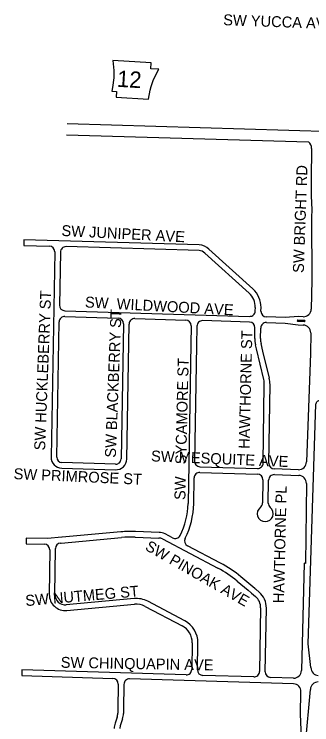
# Model space of a CAD drawing. Extents: x 0 to 712119, y 0 to 761125.
# Drawn here: x 652253 to 653613, y 733617 to 736871 of the extents above; entities that cross this region are included whole.
import ezdxf

# ---------------------------------------------------------------- set-up
doc = ezdxf.new("R2010")
doc.units = 0
for name, color, linetype in [('HWY signs', 7, 'Continuous'), ('PAVED ROADS', 7, 'Continuous'), ('street names', 7, 'Continuous')]:
    doc.layers.add(name, color=color, linetype=linetype)

msp = doc.modelspace()

# ---------------------------------------------------------------- linework, layer by layer
at = {"layer": 'HWY signs'}
msp.add_lwpolyline([(652867.2, 736482.6), (652873.6, 736523), (652878.3, 736540.7), (652888.6, 736567.4), (652899.3, 736589.8), (652914.1, 736618.9), (652877.1, 736621.1), (652878.8, 736648.5), (652703.3, 736659.1), (652708.8, 736613.5), (652708.2, 736580.4), (652702.7, 736536.1), (652699.7, 736518.6), (652719.9, 736517.4), (652718.4, 736491.6)], close=True, dxfattribs=at)
at = {"layer": 'PAVED ROADS'}
for points in [[(653710.8, 736333.1), (652495, 736368.5)], [(652492.3, 736318.6), (653597.7, 736286.4)], [(653612.4, 736256.3), (653610.7, 736117.7), (653610.7, 736039.1), (653612.6, 735974.7), (653612.1, 735941), (653612.1, 735941), (653612.8, 735653.9), (653610.4, 735520.7)], [(653098.6, 735814.5), (652296.6, 735838.5), (652296.2, 735812.5), (652412.9, 735809)], [(652437.7, 735783.1), (652421.2, 734842.8)], [(652463.6, 735781.6), (652459.4, 735539)], [(653097.8, 735788.5), (652489.9, 735806.7)], [(653343.7, 735613.3), (653142.3, 735794.9)], [(653326.3, 735594), (653123.4, 735777.1)], [(653354.8, 735512.4), (653355, 735527.9)], [(653380.7, 735510.9), (653381, 735527.4)], [(652484.1, 735513.1), (653328.5, 735487.3)], [(652484.3, 735487), (652727.2, 735479.6)], [(652447.2, 734842.3), (652458, 735462)], [(652804.2, 735477.3), (653037.1, 735470.2)], [(653328.7, 735461.3), (653114.1, 735467.9)], [(653573.8, 735485.9), (653551.6, 735486.6), (653491.5, 735482.4), (653405.5, 735485)], [(653405.7, 735459), (653490.7, 735456.4), (653550.5, 735448.6), (653550.5, 735448.6)], [(653579.3, 735463.7), (653549.3, 735464.6)], [(653549.5, 735470.6), (653579.5, 735469.7)], [(653579.3, 735463.7), (653579.3, 735463.7)], [(652751.9, 735453.7), (652741.1, 734834.3)], [(652767.1, 734833.9), (652777.9, 735452.3)], [(653061.8, 735444.3), (653060.3, 735360), (653047.3, 734630.1)], [(653087.8, 735442.8), (653086.2, 735353.9), (653076.7, 734824.9)], [(653352.5, 735386.1), (653353.4, 735435.4)], [(653378.5, 735385.7), (653379.4, 735433.9)], [(653550.5, 735448.6), (653573.9, 735447.9)], [(653608.4, 735411.7), (653606.6, 735317.9), (653588.9, 734821)], [(653360.1, 735339.3), (653355.7, 735357.8)], [(653419, 735203.9), (653389.4, 735328.5), (653380.9, 735363.8)], [(653393.7, 735197.8), (653360.1, 735339.3)], [(653390.7, 734816.1), (653396.1, 735176.2)], [(653416.7, 734814.5), (653422.1, 735175.8)], [(653609, 733878.9), (653596.4, 733988.2), (653632.3, 735085.4), (653633, 735089.1), (653634.3, 735092.6), (653636.3, 735095.8), (653638.8, 735098.7), (653641.8, 735101), (653645.2, 735102.7), (653648.8, 735103.8), (653652.5, 735104.2), (653669.6, 735105.8), (653705.1, 735106), (653712.9, 735106), (653721.7, 735105.8), (653769.3, 735104.4), (653783.5, 735104), (653814.4, 735103.1), (653842.7, 735102.3), (653872.2, 735101.1), (653896.8, 735100), (653930.7, 735098.6), (653954, 735097.9), (653976.4, 735097.2)], [(652716.4, 734810.8), (652470.5, 734817.9)], [(652469.7, 734791.9), (652715.6, 734784.8)], [(653101.4, 734799), (653364.5, 734791)], [(653101.6, 734772.9), (653364.9, 734765)], [(653551.8, 734785.3), (653441.5, 734788.6)], [(653073.3, 734629.6), (653075.3, 734747.9)], [(653389.6, 734739.1), (653388, 734632.8)], [(653441.9, 734762.6), (653553.3, 734759.2)], [(653414, 734632.4), (653415.6, 734737.5)], [(653588.2, 734722.4), (653584, 734355.3), (653578.2, 734356.9), (653565.8, 733865.3)], [(652740.3, 734500.6), (652472.3, 734476.1), (652470.6, 734476.1), (652405, 734470.1), (652308.1, 734471.5), (652307.2, 734445.5), (652389.8, 734444.3)], [(652915.1, 734498.3), (652806.5, 734502.4)], [(652976.5, 734473), (652942.1, 734491.1)], [(652464.2, 734449.4), (652467.3, 734449.5), (652742.7, 734474.7)], [(652805.5, 734476.4), (652914.1, 734472.3)], [(652930, 734468.1), (653184.1, 734334.2)], [(652414.9, 734418.5), (652413, 734214.1)], [(652439, 734213.8), (652441, 734424.6), (652441, 734424.6)], [(653196.2, 734357.2), (653044.6, 734437.1)], [(653372.4, 734224.4), (653356.6, 734237.8), (653356.3, 734238), (653352.1, 734241.6), (653288.6, 734294.9)], [(653271.8, 734275), (653322, 734233), (653336, 734221.1), (653337.3, 734220.1), (653355.6, 734204.5)], [(652800.4, 734195), (652490.3, 734166.6)], [(652492.7, 734140.7), (652802.8, 734169.1)], [(652851.3, 734159.5), (653020, 734070.6)], [(653032.1, 734093.6), (652863.4, 734182.5)], [(653379.3, 734152.2), (653374.3, 733861.3)], [(653400.2, 733859.8), (653405.3, 734151.8)], [(653066.5, 733992.1), (653064.4, 733870.7)], [(653090.4, 733869.2), (653092.5, 733991.7)], [(653038.1, 733845.6), (652288.2, 733868.4), (652287.4, 733842.3), (652703.4, 733829.8)], [(653529.9, 733804.7), (652780.4, 733827.4)], [(653348, 733836.2), (653115.1, 733843.3)], [(653530, 733830.7), (653425, 733833.9)], [(652728.2, 733803.8), (652726.2, 733688.7), (652726, 733669.9)], [(652754.1, 733802.4), (652752.3, 733688), (652752, 733669.5)], [(653623.9, 731094.8), (653552.8, 731124.8), (653532.2, 731177.3), (653583.8, 733527.6), (653606.8, 733778.9)], [(653565.2, 733547.2), (653565.3, 733557.3), (653560.8, 733665.2), (653563.4, 733768.4)], [(652722.9, 733651.8), (652714.2, 733625.2)], [(652747.6, 733643.7), (652739, 733617.1)]]:
    msp.add_lwpolyline(points, dxfattribs=at)
for centre, radius, start, end in [((653572.1, 736255.2), 40.3, 1.4945, 50.5503), ((653096.7, 735751.5), 63, 43.5707, 88.2844), ((652412.2, 735783.5), 25.5, 358.9967, 88.2861), ((652489.1, 735781.2), 25.5, 88.2861, 178.9967), ((653096.7, 735751.5), 37, 43.6506, 88.289), ((653268, 735529.4), 87, 358.9967, 47.947), ((653268, 735529.4), 113, 358.9967, 47.947), ((652484.9, 735538.5), 25.5, 178.9967, 268.256), ((653574.9, 735521.4), 35.5, 268.256, 358.9459), ((652483.5, 735461.5), 25.5, 88.256, 178.9967), ((653329.3, 735512.8), 25.5, 268.256, 358.9967), ((653406.2, 735510.5), 25.5, 178.9967, 268.247), ((652726.4, 735454.2), 25.5, 358.9967, 88.256), ((652803.4, 735451.8), 25.5, 88.256, 178.9967), ((653036.3, 735444.7), 25.5, 358.9967, 88.256), ((653113.3, 735442.4), 25.5, 88.256, 178.9984), ((653327.9, 735435.8), 25.5, 358.9967, 88.256), ((653404.9, 735433.5), 25.5, 88.256, 178.9967), ((653549.4, 735467.6), 3, 88.256, 268.256), ((653579.4, 735466.7), 3, 268.256, 88.256), ((653572.9, 735412.4), 35.5, 358.9459, 88.256), ((653465.5, 735384.1), 113, 178.9967, 193.5079), ((653465.5, 735384.1), 87, 178.9967, 193.5079), ((653309.1, 735177.5), 87, 359.1486, 13.5154), ((653309.1, 735177.5), 113, 359.1486, 13.5154), ((652471.2, 734841.9), 50, 178.9967, 268.3309), ((652471.2, 734841.9), 24, 178.9967, 268.3309), ((652717.1, 734834.8), 50, 268.3212, 358.9967), ((652717.1, 734834.8), 24, 268.3106, 358.9967), ((653102.2, 734824.4), 25.5, 179.0042, 268.2635), ((653365.2, 734816.5), 25.5, 268.2635, 359.1486), ((653442.2, 734814.1), 25.5, 179.1486, 268.2635), ((653552.9, 734821.3), 36, 268.2589, 359.5444), ((653100.8, 734747.4), 25.5, 88.2635, 179.0042), ((653364.1, 734739.5), 25.5, 359.1486, 88.2635), ((653441.1, 734737.1), 25.5, 88.2635, 179.1486), ((653552.2, 734723.3), 36, 358.5596, 88.2627), ((652710.3, 734636), 337, 333.2055, 359.0042), ((652710.3, 734636), 363, 333.0106, 359.0042), ((653400.3, 734584), 36.5, 127.5354, 50.7617), ((653362.5, 734633.2), 25.5, 307.5354, 359.1486), ((653439.5, 734632.1), 25.5, 179.1486, 230.7617), ((652787.1, 733989.8), 513, 87.8333, 95.2353), ((652912.7, 734435.3), 63, 62.222, 87.8333), ((652988.4, 734495.5), 25.5, 242.222, 333.2055), ((652465.8, 734424.6), 24.8, 93.6678, 180.0831), ((652787.1, 733989.8), 487, 87.8333, 95.2353), ((652912.7, 734435.3), 37, 62.222, 87.8333), ((653056.5, 734459.6), 25.5, 153.0106, 242.222), ((652389.4, 734418.8), 25.5, 359.4675, 89.1582), ((652957.2, 733903.3), 513, 49.7492, 62.222), ((652957.2, 733903.3), 487, 49.7492, 62.222), ((653312.3, 734153.4), 93, 359.0042, 49.7492), ((652486, 734213.4), 73, 179.4563, 275.2353), ((652486, 734213.4), 47, 179.4563, 275.2353), ((652810.8, 734082.5), 113, 62.2306, 95.2353), ((653312.3, 734153.4), 67, 359.0042, 49.7492), ((652810.8, 734082.5), 87, 62.2306, 95.2353), ((652979.5, 733993.6), 113, 359.0042, 62.2306), ((652979.5, 733993.6), 87, 359.0042, 62.2306), ((653038.9, 733871.1), 25.5, 268.2635, 359.0042), ((653115.8, 733868.8), 25.5, 179.0042, 268.2635), ((653348.8, 733861.7), 25.5, 268.2635, 359.0042), ((653425.7, 733859.4), 25.5, 179.0042, 268.2635), ((653530.3, 733866.2), 35.5, 269.4607, 358.5596), ((653644, 733878.1), 35, 178.7487, 268.3333), ((652702.7, 733804.3), 25.5, 359.0042, 88.2635), ((652779.6, 733801.9), 25.5, 88.2635, 179.0042), ((653527.9, 733769.3), 35.5, 358.5596, 86.7541), ((653641.8, 733778.1), 35, 88.3333, 178.7487), ((652664, 733671), 62, 341.9366, 359.0189), ((652664, 733671), 88, 341.9366, 359.0189), ((652797.9, 733597.9), 88, 161.9366, 178.5014), ((652797.9, 733597.9), 62, 161.9366, 178.4853)]:
    msp.add_arc(centre, radius, start, end, dxfattribs=at)

# ---------------------------------------------------------------- texts
at = {"layer": 'HWY signs'}
msp.add_text('12', height=75, rotation=356.5521, dxfattribs=at).set_placement((652721.2, 736539))
at = {"layer": 'street names'}
for s, rotation, p in [('SW YUCCA AVE', 357.9335, (653207.4, 736821)), ('SW BRIGHT RD', 87.9838, (653576.3, 735685.7)), ('SW JUNIPER AVE', 357.0269, (652467.7, 735856)), ('SW HUCKLEBERRY ST', 87.7852, (652393.7, 734873)), ('SW  WILDWOOD AVE', 356.9163, (652575.3, 735528.5)), ('SW BLACKBERRY ST', 87.7852, (652717.2, 734839.7)), ('HAWTHORNE ST', 88.6343, (653328.6, 734880.5)), ('SW   SYCAMORE ST', 88.6343, (653035, 734646.2)), ('SW MESQUITE AVE', 357.6106, (652877.5, 734823.6)), ('SW PRIMROSE ST', 357.4477, (652249.2, 734742.4)), ('HAWTHORNE PL', 88.6343, (653485.8, 734173.4)), ('SW PINOAK AVE', 330.1864, (652847.5, 734420.4)), ('SW NUTMEG ST', 4.9247, (652305.8, 734160.5)), ('SW CHINQUAPIN AVE', 358.9838, (652465.2, 733878.3))]:
    msp.add_text(s, height=50, rotation=rotation, dxfattribs=at).set_placement(p)

doc.saveas('drawing.dxf')
